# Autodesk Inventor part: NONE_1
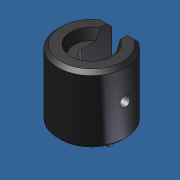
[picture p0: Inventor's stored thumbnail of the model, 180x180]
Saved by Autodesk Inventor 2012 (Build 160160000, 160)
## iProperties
Created: 2013-10
Part Number: NONE_1
Material: Default
Document SubType Name: Modeling
Designer: Admin
Density: 1 g/cm^3
Author: Admin
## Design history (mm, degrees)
node "Sankq_Base_20x201"
node "Base1"
body "Solid1"
